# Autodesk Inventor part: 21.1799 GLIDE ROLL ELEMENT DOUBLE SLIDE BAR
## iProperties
Created: 2007-05
Part Number: 21.1799 GLIDE ROLL ELEMENT DOUBLE SLIDE BAR
Material: UHMW, Black
Document SubType Name: Modeling
Designer: Andy Moles
Density: 0.94 g/cm^3
Author: Andy Moles
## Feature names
1. Extrusion1
2. Extrusion2
3. Extrusion3
4. Extrusion4
5. Extrusion5
6. Extrusion6
7. Extrusion7
